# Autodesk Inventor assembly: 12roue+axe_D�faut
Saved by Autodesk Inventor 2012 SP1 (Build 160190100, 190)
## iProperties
Created: 2011-01
Part Number: 12roue+axe_D�faut
Document SubType Name: Assembly
Designer: eric
Mass: 62.4241 g
Surface Area: 248.334 cm^2
Volume: 62.4241 cm^3
Density: 1 g/cm^3
Author: eric
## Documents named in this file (3)
- D:\Cours\Inventor salle SI\chariot_de_golf_2008\chariot_de_golf_trolem\12roue+axe_Defaut.iam
- D:\Cours\Inventor salle SI\chariot_de_golf_2008\chariot_de_golf_trolem\12axe-roue-helicoidale_Defaut.ipt
- D:\Cours\Inventor salle SI\chariot_de_golf_2008\chariot_de_golf_trolem\12Roue helicoidale_Defaut.ipt
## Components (2 placed, 2 different names)
1. 12axe-roue-helicoidale_Defaut:1
2. 12Roue helicoidale_Defaut:1
